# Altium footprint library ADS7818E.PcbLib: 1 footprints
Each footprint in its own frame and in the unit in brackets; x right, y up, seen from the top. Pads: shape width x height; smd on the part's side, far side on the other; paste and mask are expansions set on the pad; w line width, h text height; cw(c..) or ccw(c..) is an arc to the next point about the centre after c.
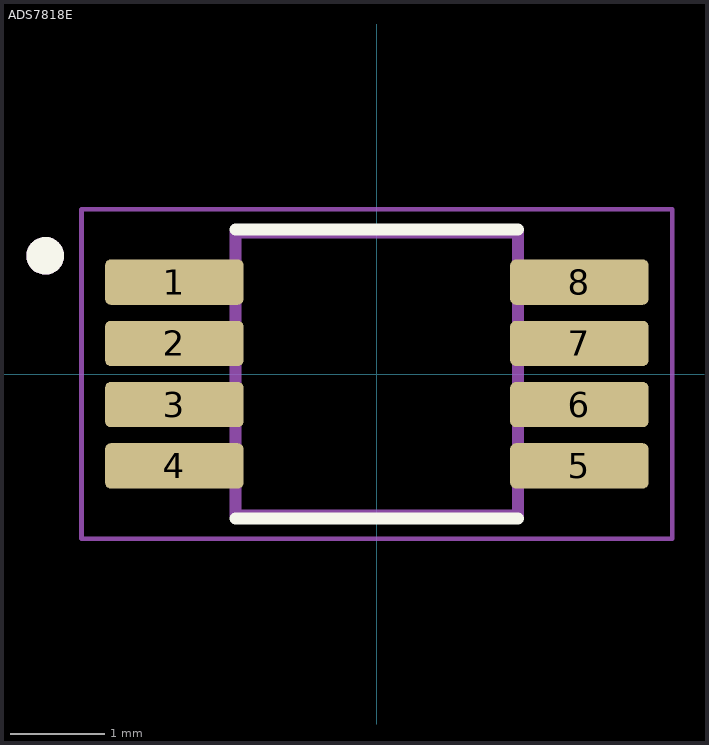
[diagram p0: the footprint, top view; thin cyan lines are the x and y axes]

## ADS7818E [mm]
pads (8):
  rrect25% 1.47x0.48 smd: 1(-2.15,0.975) 2(-2.15,0.325) 3(-2.15,-0.325) 4(-2.15,-0.975) 5(2.15,-0.975) 6(2.15,-0.325) 7(2.15,0.325) 8(2.15,0.975)
Top Overlay:
  circle w0.2: c-3.52,1.255 r0.1
  lines w0.127: -1.5,-1.535 1.5,-1.535 ; -1.5,1.535 1.5,1.535
Mechanical 13:
  circle w0.2: c-3.52,1.255 r0.1
  lines w0.127: -1.5,-1.5 -1.5,1.5 1.5,1.5 1.5,-1.5 -1.5,-1.5
Mechanical 15:
  lines w0.05: -3.135,-1.75 -3.135,1.75 3.135,1.75 3.135,-1.75 -3.135,-1.75
3D body "ADS7818E.STEP": height 1.1, standoff 0, extent -2.484,-1.51 2.416,1.49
